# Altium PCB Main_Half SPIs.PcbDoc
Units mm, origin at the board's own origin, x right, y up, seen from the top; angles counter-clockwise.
Board outline 64.93 x 46.99 mm, 2 copper layers (Top Layer, Bottom Layer); 51 components, 38 nets, 223 pads, 38 vias.
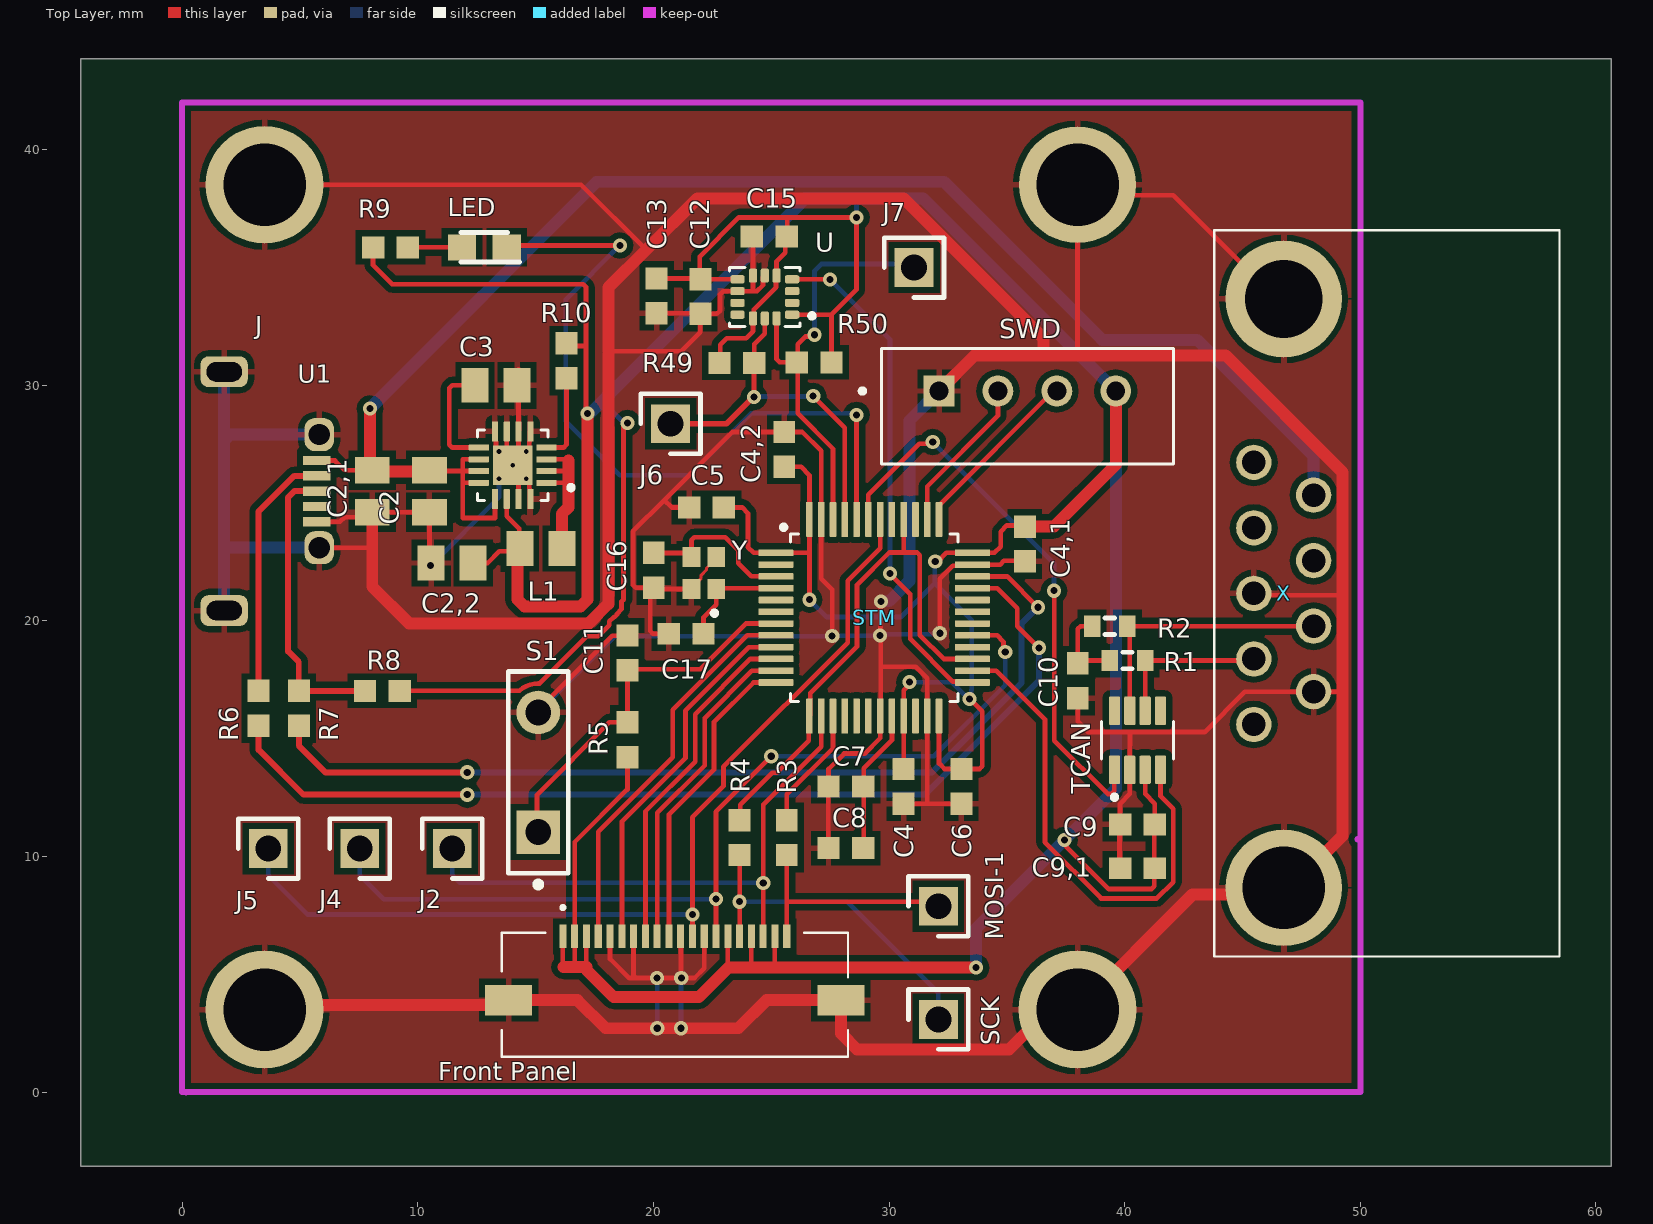
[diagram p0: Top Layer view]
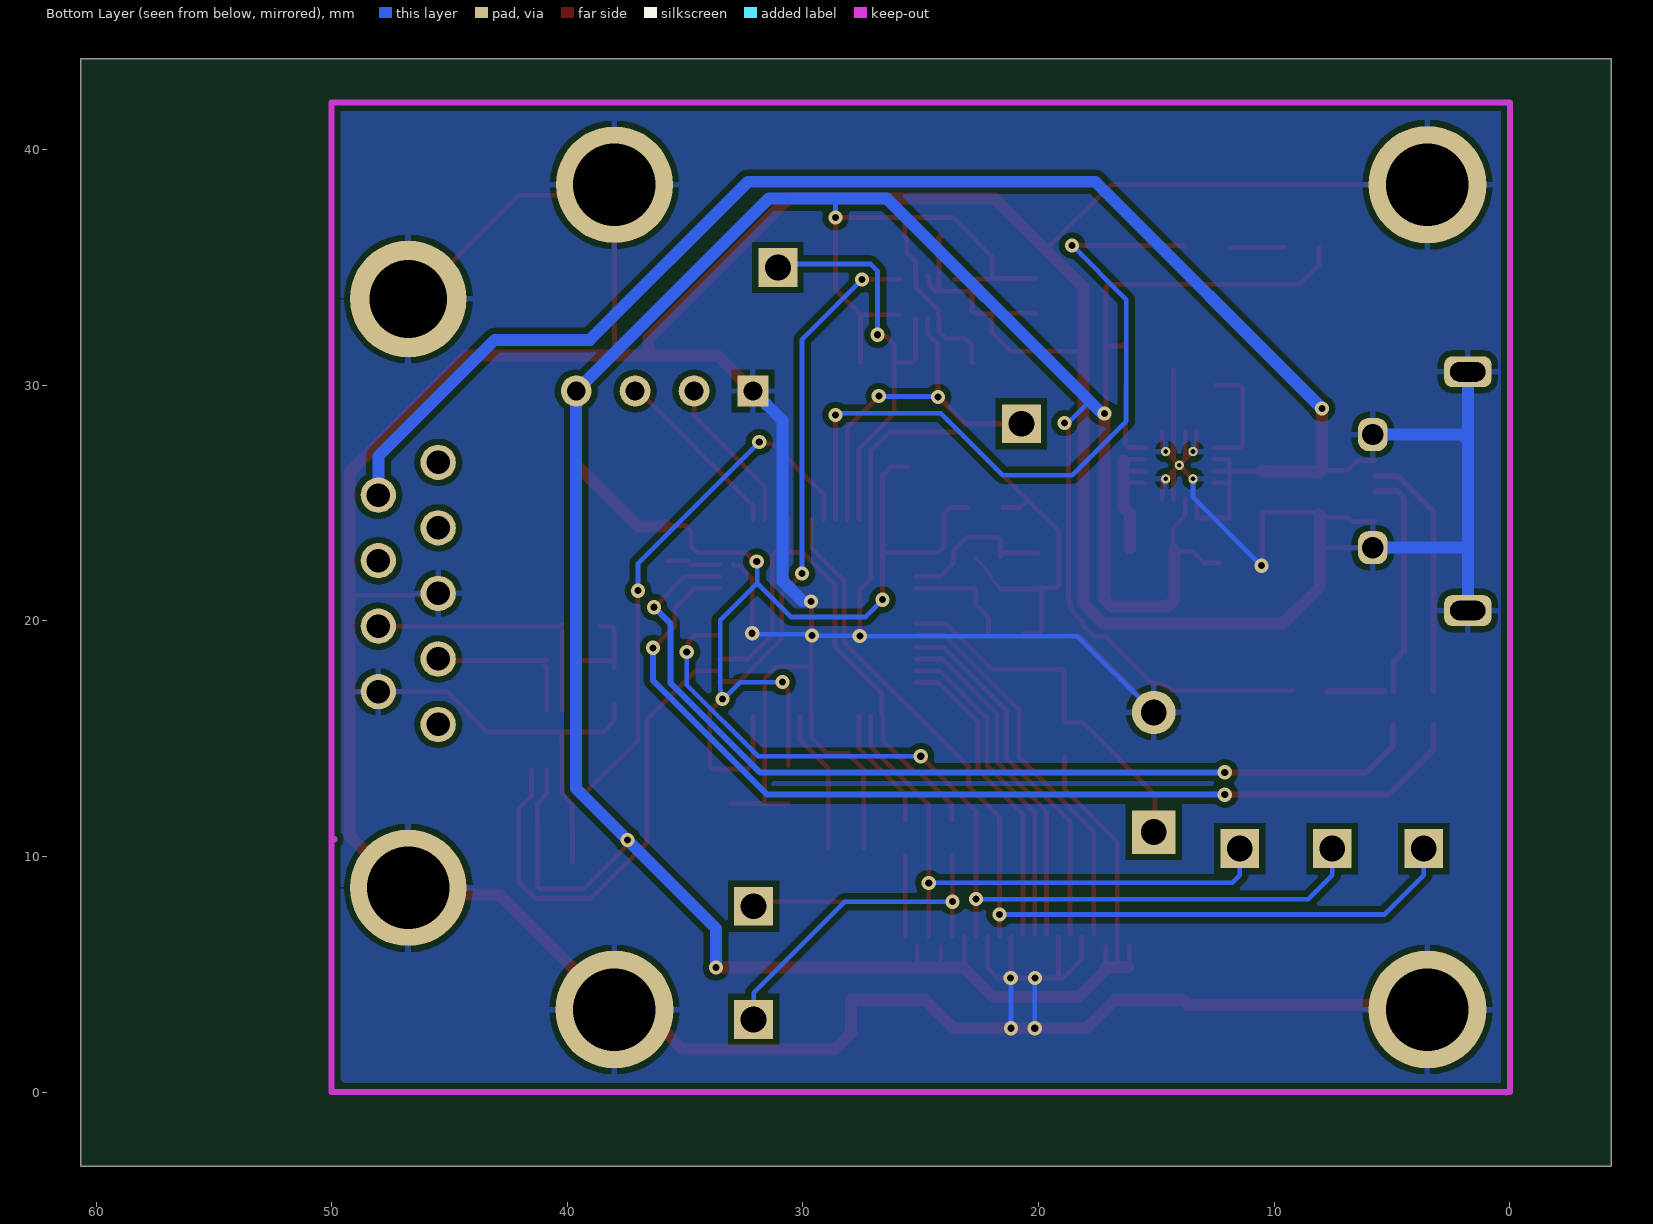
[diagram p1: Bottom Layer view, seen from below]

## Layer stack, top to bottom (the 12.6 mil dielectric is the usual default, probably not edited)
Top Solder: solder mask 0.0102, Solder Resist, Dk 3.5
Top Layer: signal copper 0.0356
Dielectric 1: dielectric 0.32, FR-4, Dk 4.8
Bottom Layer: signal copper 0.0356
Bottom Solder: solder mask 0.0102, Solder Resist, Dk 3.5

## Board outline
-4.291,-3.153 60.641,-3.153 60.641,43.841 -4.291,43.841

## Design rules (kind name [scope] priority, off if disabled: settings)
Clearance [All] p1: gap=0.254 ignorepadtopadclearanceinfootprint=TRUE except(0: Arc-Hole Track-Hole SMDPad-Hole THPad-Hole Fill-Hole Poly-Hole Region-Hole; 0.127: SMDPad-SMDPad SMDPad-THPad THPad-THPad; 0.15: Arc-Text Track-Text SMDPad-Text THPad-Text Via-Text Fill-Text Poly-Text Region-Text Text-Text Text-Hole; 0.2: Arc-Arc Arc-Track Arc-SMDPad Arc-THPad Track-Track Track-SMDPad Track-THPad; 0.5: Via-Hole)
ComponentClearance [All] p1: gap=0 collisioncheckmode=3 verticalgap=0 showdistances=FALSE
DiffPairsRouting TCAN [InDifferentialPair('TCAN')] p1: maxlimit=0.254 minlimit=0.254 mostfreqgap=0.254 toplayer_minwidth=0.2 toplayer_maxwidth=0.381 toplayer_prefwidth=0.2 bottomlayer_minwidth=0.2 bottomlayer_maxwidth=0.381 bottomlayer_prefwidth=0.2 maxuncoupledlength=12.7
HoleSize [All] p1: absolutevalues=TRUE maxlimit=4 minlimit=0.025 maxpercent=80.000 minpercent=20.000
HoleToHoleClearance [All] p1: gap=0.5 allowstackedmicrovias=TRUE
MatchedLengths MatchedLengths_1 [InDifferentialPair ('TCAN')] p1: tolerance=25.4 checknetsindiffpair=FALSE checkdiffpairvsdiffpair=TRUE checkxsignals=TRUE checkothers=TRUE
MatchedLengths CANMatchedLengths [InDifferentialPair ('TCAN')] p2: tolerance=25.4 checknetsindiffpair=FALSE checkdiffpairvsdiffpair=TRUE checkxsignals=TRUE checkothers=TRUE
MatchedLengths [InDifferentialPair ('NewDifferentialPair1')] p3: tolerance=25.4 checknetsindiffpair=FALSE checkdiffpairvsdiffpair=TRUE checkxsignals=TRUE checkothers=TRUE
MinimumSolderMaskSliver [All] p1: minsoldermaskwidth=0.2
PlaneConnect PlaneConnect_1 [All] p1: planeconnectstyle=Relief reliefexpansion=0.508 reliefentries=4 reliefconductorwidth=0.254 reliefairgap=0.254
PlaneConnect PlaneConnect_2 [IsPad] p2: planeconnectstyle=Relief reliefexpansion=0.508 reliefentries=4 reliefconductorwidth=0.254 reliefairgap=0.254
PlaneConnect [All] p3: planeconnectstyle=Relief reliefexpansion=0.508 reliefentries=4 reliefconductorwidth=0.254 reliefairgap=0.254
PolygonConnect PolygonConnect_2 [ispad] p1: thpad.connectstyle=Relief thpad.reliefconductorwidth=0.254 thpad.reliefentries=4 thpad.polygonreliefangle="90 Angle" thpad.airgapwidth=0.254 smdpad.connectstyle=Relief smdpad.reliefconductorwidth=0.254 smdpad.reliefentries=4 smdpad.polygonreliefangle="90 Angle" smdpad.airgapwidth=0.254 via.connectstyle=Direct via.reliefconductorwidth=0.254 via.reliefentries=4 via.polygonreliefangle="90 Angle" via.airgapwidth=0.254
PolygonConnect PolygonConnect_1 [All] p2: connectstyle=Direct reliefconductorwidth=0.254 reliefentries=4 polygonreliefangle="90 Angle" airgapwidth=0.254
PolygonConnect [All] p3: connectstyle=Relief reliefconductorwidth=0.254 reliefentries=4 polygonreliefangle="90 Angle" airgapwidth=0.254
RoutingTopology [All] p1: topology=Daisy_MidDriven
RoutingVias [All] p1: holewidth=0.3 width=0.6 viastyle="Through Hole" minholewidth=0.3 minwidth=0.6 maxholewidth=0.3 maxwidth=0.6
SolderMaskExpansion [All] p1: expansion=0.05 istentingtop=FALSE
Width Width_1 [All] p1: maxlimit=0.508 minlimit=0.127 preferedwidth=0.2
23 further rules are at their usual default settings.

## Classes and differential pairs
differential pair USB: +NetJ_3 -NetJ_2
differential pair USB1: +USB_DP -USB_DM
differential pair TCAN: +CAN_P -CAN_N

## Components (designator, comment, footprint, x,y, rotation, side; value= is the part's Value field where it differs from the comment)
C2 "Cap" INDC2012X55N 10.5,25.497 r270 top value=0.1uF
C2,1 "Cap" INDC2012X55N 8.072,25.497 r270 top value=10uF
C2,2 "Cap" INDC2012X55N 11.462,22.451 r0 top value=22uF
C3 "Cap" INDC2012X55N 13.325,29.989 r180 top value=3.3nF
C4 "Cap" CAPC1608X90N 30.624,12.971 r270 top value=100nF
C4,1 "Cap" CAPC1608X90N 35.765,23.258 r270 top value=100nF
C4,2 "Cap" CAPC1608X90N 25.555,27.271 r90 top value=100nF
C5 "Cap" CAPC1608X90N 22.257,24.807 r180 top value=10uF
C6 "Cap" CAPC1608X90N 33.073,12.971 r270 top value=1uF
C7 "Cap" CAPC1608X90N 28.171,12.971 r180 top value=1uF
C8 "Cap" CAPC1608X90N 28.171,10.349 r180 top value=100nF
C9 "Cap" CAPC1608X90N 40.543,11.354 r180 top value=100nF
C9,1 "Cap" CAPC1608X90N 40.543,9.497 r180 top value=100nF
C10 "Cap" CAPC1608X90N 38.01,17.456 r270 top value=4.7nF
C11 "Cap" CAPC1608X90N 18.9,18.635 r90 top value=100nF
C12 "Cap" CAPC1608X90N 20.141,33.785 r90 top value=0.1uF
C13 "Cap" CAPC1608X90N 21.996,33.759 r270 top value=2.22uF
C15 "Cap" CAPC1608X90N 24.917,36.299 r0 top value=10nF
C16 "Cap" CAPC1608X90N 20.017,22.14 r270 top value=8pF
C17 "Cap" CAPC1608X90N 21.389,19.448 r180 top value=8pF
"Front Panel" "5051102091" 5051102091 20.911,4.128 r0 top locked
J "47654-0001" USB_Conector 1.791,25.499 r270 top
J2 "90120-0761" HDRV1W90P0X254_1X1_232X249X560P 11.466,10.331 r90 top
J4 "90120-0761" HDRV1W90P0X254_1X1_232X249X560P 7.542,10.331 r90 top
J5 "90120-0761" HDRV1W90P0X254_1X1_232X249X560P 3.658,10.331 r90 top
J6 "90120-0761" HDRV1W90P0X254_1X1_232X249X560P 20.732,28.36 r90 top
J7 "90120-0761" HDRV1W90P0X254_1X1_232X249X560P 31.064,34.988 r90 top
L1 "Inductor" INDC2012X55N 15.23,23.063 r180 top value=1/2.2uH
LED "17-21_GHC-YR1S2_3T" LEDM2012X110N 12.827,35.847 r180 top
MOSI-1 "90120-0761" HDRV1W90P0X254_1X1_232X249X560P 32.094,7.884 r90 top (schematic designator J1)
R1 "Res3" J1-0603 40.118,18.309 r0 top value=60
R2 "Res3" J1-0603 39.368,19.77 r180 top value=60
R3 "Res" CAPC1608X90N 25.661,10.799 r90 top value=100
R4 "Res" CAPC1608X90N 23.661,10.799 r90 top value=100
R5 "Res" CAPC1608X90N 18.9,14.952 r270 top value=60
R6 "Res" CAPC1608X90N 3.253,16.29 r90 top value=22
R7 "Res" CAPC1608X90N 4.956,16.29 r90 top value=22
R8 "Res" CAPC1608X90N 8.501,17.025 r180 top value=1.5k
R9 "Res" CAPC1608X90N 8.845,35.847 r180 top value=1.5k
R10 "Res" CAPC1608X90N 16.313,31.031 r270 top value=100k (schematic designator R?)
R49 "Res" CAPC1608X90N 23.546,30.94 r180 top value=10k
R50 "Res" CAPC1608X90N 26.822,30.965 r0 top value=10k
S1 "SW-PB" SPST-2 15.115,13.568 r90 top
SCK "90120-0761" HDRV1W90P0X254_1X1_232X249X560P 32.094,3.082 r90 top (schematic designator J3)
STM "STM32G473CET6" QFP50P900X900X160-48N 29.374,20.13 r0 top value=Value
SWD "22-03-5045" MOLEX_22-03-5045 35.874,29.099 r0 top
TCAN "TCAN332GD" SOT65P280X145-8N 40.543,14.927 r90 top
U "ICM-42605" PQFN50P300X250X97-14N 24.73,33.738 r180 top
U1 "TPS62132RGTR" QFN50P300X300X100-17N 14.03,26.6 r180 top
X "DSUB9" 23018431 45.48,15.6 r90 top
Y "ECS-160-9-37-CKM-TR" XTAL_ECS-160-9-37-CKM-TR 22.143,22.022 r90 top

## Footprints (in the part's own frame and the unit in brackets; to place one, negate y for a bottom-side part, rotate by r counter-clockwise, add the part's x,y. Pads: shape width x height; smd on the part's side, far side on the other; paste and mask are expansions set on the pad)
23018431 [mm]
  round 1.5 hole 1: 1(0,0) 2(2.78,0) 3(5.56,0) 4(8.34,0) 5(11.12,0) 6(1.39,-2.54) 7(4.17,-2.54) 8(6.95,-2.54) 9(9.73,-2.54)
  round 4.95 hole 3.5 paste+0: MH2(-6.935,-1.27)
  round 4.95 hole 3.3 mask+0.05: MH2(18.055,-1.27)
  silkscreen extent -9.85,-12.97 20.96,1.68, body extent -9.86,-18.95 20.95,1.7, height 13.59
5051102091 [mm]
  rect 0.3x1 smd: 1(-4.75,2.475) 2(-4.25,2.475) 3(-3.75,2.475) 4(-3.25,2.475) 5(-2.75,2.475) 6(-2.25,2.475) 7(-1.75,2.475) 8(-1.25,2.475) 9(-0.75,2.475) 10(-0.25,2.475) 11(0.25,2.475) 12(0.75,2.475) 13(1.25,2.475) 14(1.75,2.475) 15(2.25,2.475) 16(2.75,2.475) 17(3.25,2.475) 18(3.75,2.475) 19(4.25,2.475) 20(4.75,2.475)
  rect 2x1.3 smd: MP1(-7.05,-0.225) MP2(7.05,-0.225)
  silkscreen extent -7.35,-2.63 7.35,3.75, body extent -7.75,-2.64 7.75,2.66, height 1.88
CAPC1608X90N [mm]
  rect 0.95x0.93 smd: 1(-0.738,0) 2(0.738,0)
HDRV1W90P0X254_1X1_232X249X560P [mm]
  rect 1.65x1.65 hole 1.1: 1(0,0)
  silkscreen extent -1.27,-1.27 1.27,1.27, body extent -1.27,-1.25 1.27,1.25, height 9.25
INDC2012X55N [mm]
  rect 1.14x1.47 smd: 1(-0.89,0) 2(0.89,0)
J1-0603 [mm] "Chip Resistor, Body 1.6x0.8mm, IPC High Density"
  rect 0.7x0.9 smd: 1(-0.75,0) 2(0.75,0)
  silkscreen extent -0.2,-0.35 0.2,0.35, body extent -0.85,-0.48 0.85,0.48, height 0.9
LEDM2012X110N [mm]
  rect 1.2x1.1 smd: 1(-0.95,0) 2(0.95,0)
  silkscreen extent -1.5,-0.63 1,0.63
MOLEX_22-03-5045 [mm]
  rect 1.308x1.308 hole 0.8: 1(-3.75,0.65)
  round 1.308 hole 0.8: 2(-1.25,0.65) 3(1.25,0.65) 4(3.75,0.65)
  silkscreen extent -7.1,-2.45 6.2,2.45
PQFN50P300X250X97-14N [mm]
  rrect50% 0.61x0.35 smd: 1(-1.16,0.75) 2(-1.16,0.25) 3(-1.16,-0.25) 4(-1.16,-0.75) 8(1.16,-0.75) 9(1.16,-0.25) 10(1.16,0.25) 11(1.16,0.75)
  rrect50% 0.35x0.61 smd: 5(-0.5,-0.91) 6(0,-0.91) 7(0.5,-0.91) 12(0.5,0.91) 13(0,0.91) 14(-0.5,0.91)
  silkscreen extent -2.1,-1.25 1.5,1.25
QFN50P300X300X100-17N [mm]
  rrect25% 0.86x0.26 smd: 1(-1.435,0.75) 2(-1.435,0.25) 3(-1.435,-0.25) 4(-1.435,-0.75) 9(1.435,-0.75) 10(1.435,-0.25) 11(1.435,0.25) 12(1.435,0.75)
  rrect25% 0.26x0.86 smd: 5(-0.75,-1.435) 6(-0.25,-1.435) 7(0.25,-1.435) 8(0.75,-1.435) 13(0.75,1.435) 14(0.25,1.435) 15(-0.25,1.435) 16(-0.75,1.435)
  rect 1.68x1.68 smd paste-2: 17(0,0)
  round 0.4 hole 0.2 mask+0: 18(0,0) 19(-0.58,0.58) 20(0.58,0.58) 21(-0.58,-0.58) 22(0.58,-0.58)
  silkscreen extent -2.57,-1.5 1.5,1.5
QFP50P900X900X160-48N [mm]
  rrect25% 1.49x0.28 smd: 1(-4.17,2.75) 2(-4.17,2.25) 3(-4.17,1.75) 4(-4.17,1.25) 5(-4.17,0.75) 6(-4.17,0.25) 7(-4.17,-0.25) 8(-4.17,-0.75) 9(-4.17,-1.25) 10(-4.17,-1.75) 11(-4.17,-2.25) 12(-4.17,-2.75) 25(4.17,-2.75) 26(4.17,-2.25) 27(4.17,-1.75) 28(4.17,-1.25) 29(4.17,-0.75) 30(4.17,-0.25) 31(4.17,0.25) 32(4.17,0.75) 33(4.17,1.25) 34(4.17,1.75) 35(4.17,2.25) 36(4.17,2.75)
  rrect25% 0.28x1.49 smd: 13(-2.75,-4.17) 14(-2.25,-4.17) 15(-1.75,-4.17) 16(-1.25,-4.17) 17(-0.75,-4.17) 18(-0.25,-4.17) 19(0.25,-4.17) 20(0.75,-4.17) 21(1.25,-4.17) 22(1.75,-4.17) 23(2.25,-4.17) 24(2.75,-4.17) 37(2.75,4.17) 38(2.25,4.17) 39(1.75,4.17) 40(1.25,4.17) 41(0.75,4.17) 42(0.25,4.17) 43(-0.25,4.17) 44(-0.75,4.17) 45(-1.25,4.17) 46(-1.75,4.17) 47(-2.25,4.17) 48(-2.75,4.17)
  silkscreen extent -3.94,-3.55 3.55,3.94
SOT65P280X145-8N [mm]
  rrect25% 1.21x0.48 smd: 1(-1.255,0.975) 2(-1.255,0.325) 3(-1.255,-0.325) 4(-1.255,-0.975) 5(1.255,-0.975) 6(1.255,-0.325) 7(1.255,0.325) 8(1.255,0.975)
  silkscreen extent -2.51,-1.54 0.8,1.54, body extent -1.4,-1.45 1.4,1.45, height 1.45
SPST-2 [mm] "Switch; 2 Leads"
  rect 1.85x1.85 hole 1.1: 1(-2.54,0)
  round 1.85 hole 1.1: 2(2.54,0)
  silkscreen extent -4.89,-1.27 4.28,1.27
USB_Conector [mm]
  rect 0.4x1.15 smd: 1(-1.3,3.925) 2(-0.65,3.925) 3(0,3.925) 4(0.65,3.925) 5(1.3,3.925)
  rrect50% 1.3x2 hole 1.5 slot 0.83 at 0 deg: 6(-5.065,0) 9(5.065,0)
  rrect70% 1.4x1.25 hole 0.9: 7(-2.4,4.03) 8(2.4,4.03)
XTAL_ECS-160-9-37-CKM-TR [mm]
  rect 0.85x0.75 smd: 1(-0.675,-0.525) 2(0.675,-0.525) 3(0.675,0.525) 4(-0.675,0.525)
  silkscreen extent -1.8,-0.55 -1.6,-0.35, body extent -1,-0.8 1,0.8, height 0.55

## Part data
C2 C2,1 C2,2 C3 C4 C4,1 C4,2 C5 C6 C7 C8 C9 C9,1 C10 C11 C12 C13 C15 C16 C17: "Capacitor"
"Front Panel": "Connector", Manufacturer_Name=Molex
J: library part 10118194-0001LF, "USB - micro B USB 2.0 Receptacle Connector 5 Position Surface Mount, Right Angle; Through Hole", Package=None
J2 J4 J5 J6 J7 MOSI-1 SCK: "Connector", Manufacturer_Name=Molex, Mouser Part Number=538-90120-0761
LED: "LED", Arrow Part Number=17-21/GHC-YR1S2/3T, Manufacturer_Name=Everlight, Mouser Part Number=N/A
R1 R2: "Resistor"
R3 R4 R5 R6 R7 R8 R9 R10 R49 R50: library part Res1, "Resistor"
S1: "Switch"
STM: library part STM32G4_LQFP48_T, "No Description Available", Manufacturer_Part_Number=stm32g4_lqfp48_t1
SWD: "Connector Header Through Hole 4 position 0.098 _2.50mm_", Package="QFP-208 Molex"
TCAN: "3.3-V CAN Transceivers with CAN FD (Flexible Data Rate) 8-SOIC -40 to 125", Package="SOIC-8 Texas Instruments"
U: "Accelerometer, Gyroscope, 6 Axis Sensor IÂ²C, I3Câ„ , SPI Output", Package="- TDK InvenSense"
U1: Package=None
X: "Connector Cap _Cover_, Screen For D-Sub Connectors, Female", Package=None
Y: "16MHz Â±10ppm Crystal 9pF 100 Ohms 4-SMD, No Lead", Package="SMD-4 ECS International"

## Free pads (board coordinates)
  round 5 hole 3.5 paste+0 mask+0.05: 2(38,3.5) 4(3.5,3.5) 5(3.5,38.5)
  round 4.95 hole 3.5 paste+0 mask+0.05: 3(38,38.5)

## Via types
v1: diameter 0.6, hole 0.3, Top Layer to Bottom Layer, tented both sides, 37 vias
v2: diameter 0.6, hole 0.3, Top Layer to Bottom Layer, 1 vias

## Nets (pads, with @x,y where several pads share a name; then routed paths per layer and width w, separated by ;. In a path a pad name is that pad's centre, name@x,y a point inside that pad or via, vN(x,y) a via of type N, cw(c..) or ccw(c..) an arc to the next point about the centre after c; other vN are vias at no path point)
3V3: "Front Panel.1" "Front Panel.2" "Front Panel.3" "Front Panel.15" "Front Panel.17" "Front Panel.19" C2,2.2 C4,1.1 C4,2.1 C4.1 C5.1 C6.1 C9,1.1 C9.1 C12.2 C13.1 C15.2 L1.2 R5.2 R8.1 R9.2 R10.1 R49.2 R50.2 STM.1 STM.21 STM.24 STM.36 STM.48 SWD.4 TCAN.3 U1.14 U.1 U.5 U.8 U.12 | length 233.9
  Top Layer w0.127: 23.161,5.51 23.39,5.281
  Top Layer w0.2: R9.2 8.107,35.082 8.913,34.276 17.028,34.276 17.145,34.159 v1@17.145,28.626 ; R8.1 14.302,17.025 cw(c15.115,16.108) 15.124,17.333 15.168,17.333 17.173,19.338 17.656,19.338 18.135,19.816 18.135,19.972 18.31,20.148 18.345,20.148 18.462,20.265 18.462,20.299 18.647,20.485 18.647,20.812 18.735,20.9 18.735,28.271 18.852,28.389 v1(18.901,28.389) ; 12.352,22.451 12.967,22.451 13.462,22.946 14.187,22.946 14.24,22.999 L1.2@14.304,23.063 ; U1.14 13.78,24.435 14.304,23.911 L1.2@14.304,23.063 ; L1.2 L1.2@14.304,23.063 ; 16.154,5.327 16.154,6.189 ; R10.1 16.427,31.655 17.028,31.655 ; 16.661,6.603 16.661,5.314 16.674,5.3 ; 16.668,6.63 16.668,10.611 18.9,12.843 R5.2 ; 17.154,5.198 17.154,5.3 17.154,6.189 ; C12.2 C13.1@21.97,34.523 ; R49.2 22.837,30.968 22.837,31.705 23.125,31.993 23.942,31.993 24.23,32.281 U.12 24.255,32.853 24.255,33.206 25.205,34.156 25.205,34.623 U.5 25.23,35.253 25.595,35.617 25.595,36.24 C15.2 25.682,36.326 25.682,37.112 ; C5.1 23.77,24.807 24.016,24.561 24.016,23.126 24.262,22.88 STM.1 26.623,22.88 ; 23.161,5.51 23.161,6.603 ; U.8 22.005,34.488 C13.1 C13.1@21.97,34.523 ; 24.154,5.281 24.154,6.189 ; 25.154,5.281 25.154,6.189 ; 25.555,26.533 26.27,26.533 26.623,26.179 STM.48 26.623,22.88 ; U.1 27.56,32.988 ; v1(26.623,20.893) 26.623,22.88 ; R50.2 27.56,32.988 ; C4.1@30.624,13.847 STM.21 30.624,17.047 30.863,17.287 v1(30.863,17.395) ; v1(31.962,22.511) 32.07,22.511 32.438,22.88 STM.36 34.473,22.88 34.737,23.143 34.737,23.781 35,24.045 35.716,24.045 35.765,23.996 35.832,24.063 ; STM.24 32.124,13.943 32.358,13.709 C6.1 33.838,13.709 33.955,13.826 33.955,16.15 v1(33.42,16.686) ; v1@37.52,10.418 39.323,8.615 41.138,8.615 41.256,8.732 41.256,9.728 C9.1@41.256,11.354 ; TCAN.3 40.868,12.649 41.281,12.236 C9.1 ; C13.1@21.97,34.523 21.97,35.455 23.627,37.112 25.682,37.112 ; 25.682,37.112 v1(28.617,37.112) 28.617,34.045 27.56,32.988
  Top Layer w0.5: 17.154,5.198 18.32,4.032 21.93,4.032 23.179,5.281 23.39,5.281
  Top Layer w0.508: L1.2@14.24,22.999 14.24,20.898 14.538,20.6 16.902,20.6 17.2,20.898 v1(17.2,28.8) ; 16.195,5.3 16.674,5.3 17.154,5.3 ; 23.39,5.281 24.154,5.281 25.154,5.281 v1(33.696,5.281) ; 35.832,24.063 35.899,23.996 36.992,23.996 39.624,26.627 SWD.4
  Bottom Layer w0.2: 17.956,29.437 17.956,29.197 18.764,28.389 v1(18.901,28.389) ; v1(26.623,20.893) 27.362,20.155 30.502,20.155 31.943,21.597 ; v1(28.617,37.112) 28.624,37.12 28.624,37.92 ; v1(30.863,17.395) 32.658,17.395 33.368,16.686 v1(33.42,16.686) 33.496,16.762 33.496,17.071 33.511,17.086 33.511,20.029 31.943,21.597 ; v1(31.962,22.511) 31.943,22.493 31.943,21.597
  Bottom Layer w0.508: v1(17.2,28.8) 17.319,28.8 v1@17.364,28.844 ; v1@17.385,28.866 17.956,29.437 26.439,37.92 28.624,37.92 31.452,37.92 SWD.4 39.624,12.873 v1(37.443,10.693) ; v1(33.696,5.281) 33.696,6.946 v1@37.413,10.663
CAN_N: R1.2 TCAN.6 X.2 | length 6.7
  Top Layer w0.2: TCAN.6 40.868,17.992 R1.2@40.968,18.092 ; R1.2@40.94,18.38 R1.2 45.409,18.309 X.2 ; R1.2@40.999,18.061 R1.2@41.034,18.096
CAN_P: R2.1 TCAN.7 X.7 | length 11.2
  Top Layer w0.2: TCAN.7 40.218,19.555 R2.1@40.225,19.562 ; R2.1@40.218,19.866 40.315,19.77 47.812,19.77 X.7@47.916,19.666
DEC_A0: "Front Panel.4" STM.8 | length 16.5
  Top Layer w0.2: 17.667,6.706 17.667,11.044 20.828,14.205 20.828,16.219 23.989,19.38 STM.8@25.191,19.38
DEC_A1: "Front Panel.6" STM.9 | length 15.5
  Top Layer w0.2: 18.667,6.706 18.667,11.479 21.361,14.173 21.361,16.186 24.054,18.88 STM.9@25.191,18.88
DEC_A2: "Front Panel.8" STM.10 | length 14.6
  Top Layer w0.2: 19.667,6.706 19.667,11.913 21.776,14.023 21.776,16.036 24.12,18.38 STM.10@25.191,18.38
DEC_E3_1: "Front Panel.9" STM.11 | length 13.9
  Top Layer w0.2: 20.167,6.706 20.167,11.847 22.176,13.857 22.176,15.87 24.186,17.88 STM.11
DEC_E3_2: "Front Panel.10" STM.12 | length 13.1
  Top Layer w0.2: 20.667,6.706 20.667,11.782 22.576,13.691 22.576,15.704 24.251,17.38 STM.12
GND: "Front Panel.5" "Front Panel.7" "Front Panel.11" "Front Panel.13" "Front Panel.MP1" "Front Panel.MP2" C2,1.2 C2,2.1 C2.2 C3.1 C4,1.2 C4,2.2 C4.2 C5.2 C6.2 C7.2 C8.2 C9,1.2 C9.2 C10.2 C11.2 C12.1 C13.2 C15.1 C16.2 C17.2 J.5 J.6 J.7 J.8 J.9 pad.2 pad.3 pad.4 pad.5 S1.2 STM.19 STM.23 STM.35 STM.47 SWD.1 TCAN.2 U1.5 U1.6 U1.7 U1.8 U1.15 U1.16 U1.17 U1.18 U1.19 U1.20 U1.21 U1.22 U.6 U.7 U.9 X.3 X.6 X.MH2 Y.2 Y.4 | length 359.7
  Top Layer w0.127: Y.4 21.618,21.397 22.029,21.808 22.029,21.935 22.256,22.162 22.256,22.235 22.668,22.647 Y.2
  Top Layer w0.2: pad.5 16.93,38.5 19.691,35.738 ; J.5 6.702,24.199 6.9,24.397 7.959,24.397 8.072,24.51 ; J.8 7.953,23.099 8.072,22.98 ; 8.072,24.607 C2.2 v2@10.5,22.415 ; v2(10.55,22.336) 10.557,22.343 v2@10.572,22.343 ; U1.8 13.31,28.005 13.31,27.6 13.325,27.585 13.325,27.305 U1.22 U1.17@13.78,26.85 ; U1.17@13.5,26.07 U1.17 ; U1.7 U1.17@13.78,26.85 ; U1.15 U1.17@14.28,26.35 ; C3.1@14.287,30.671 14.28,30.664 14.28,29.215 U1.6 14.28,26.93 U1.17@14.32,26.89 ; U1.16 14.75,25.195 14.75,25.6 14.735,25.615 14.735,25.895 U1.19 U1.17@14.28,26.35 ; U1.5 14.75,28.005 14.75,27.6 14.735,27.585 14.735,27.305 U1.21 U1.17@14.32,26.89 ; S1.2 15.115,16.231 18.252,19.368 18.895,19.368 C11.2 ; 17.956,31.437 18.093,31.437 21.186,31.437 21.996,32.246 C13.2 22.694,33.021 22.83,33.157 22.83,33.852 22.965,33.988 U.9 24.23,33.988 ; 18.161,6.603 18.161,5.649 18.974,4.836 19.257,4.836 ; 19.161,6.603 19.161,4.932 19.257,4.836 ; C12.1 C13.2@21.97,33.047 ; C17.2 19.982,19.448 19.865,19.565 19.865,21.25 C16.2 ; 21.161,6.603 21.173,6.591 21.173,4.853 v1(21.186,4.84) 21.746,4.84 22.161,5.255 22.161,6.603 ; v1@21.184,4.838 20.163,4.838 v1(20.161,4.836) 19.257,4.836 ; C5.2 20.78,24.807 20.467,25.12 ; Y.4 20.073,21.347 C16.2 ; C15.1@24.23,36.247 U.7 24.23,33.988 ; U.6 24.655,34.573 24.655,34.247 24.396,33.988 24.23,33.988 ; C8.2 27.417,10.365 27.417,12.955 C7.2 27.433,13.706 28.092,14.365 28.964,14.365 29.623,15.025 STM.19 29.654,15.99 29.654,18.049 ; v1(27.59,19.346) 27.59,21.321 27.124,21.788 STM.47 27.124,27.205 26.32,28.009 25.555,28.009 23.356,28.009 20.467,25.12 ; v1(29.659,20.809) 29.641,20.791 29.641,19.39 v1(29.623,19.372) 29.654,19.342 29.654,18.049 ; C4.2 31.624,12.233 ; v1(32.155,19.47) 32.155,21.78 32.715,22.34 32.917,22.34 STM.35@32.971,22.394 ; C6.2 31.624,12.233 ; STM.35 34.711,22.38 34.878,22.547 35.738,22.547 35.765,22.52 ; 38,31.259 pad.3 38.439,38.061 42.06,38.061 X.MH2@46.75,33.371 ; C10.2@38.01,16.504 38.01,15.729 38.462,15.277 40.225,15.277 ; 39.78,9.728 39.78,11.328 C9.2 39.805,12.236 40.218,12.649 TCAN.2 40.218,14.724 40.225,14.73 40.225,15.277 ; X.3@45.48,20.876 X.3@45.56,20.796 ; X.3 45.56,21.08 49.243,21.08 ; 49.243,16.99 X.6 45.105,16.99 43.392,15.277 40.225,15.277 ; U1.17@13.78,26.85 U1.17 ; U1.17 U1.17@14.28,26.35 ; U1.17 U1.17@14.32,26.89 ; C16.2 19.252,21.402 19.135,21.519 19.135,23.788 20.467,25.12 ; 29.654,18.049 31.134,18.049 31.624,17.56 STM.23 31.624,12.233
  Top Layer w0.254: C13.2@21.97,33.047 C13.2 ; C15.1 C15.1@24.23,36.247
  Top Layer w0.508: pad.4 3.701,3.701 13.659,3.701 13.861,3.903 16.777,3.903 17.972,2.707 v1(20.167,2.707) v1(21.167,2.707) 23.606,2.707 24.801,3.903 27.961,3.903 27.961,2.491 28.649,1.803 35.088,1.803 36.284,3 pad.2@39,3 ; 8.072,24.51 8.072,22.98 8.072,21.45 9.63,19.892 17.271,19.892 18.093,20.714 18.093,31.299 ; 18.093,31.437 18.093,34.14 19.691,35.738 21.873,37.92 30.622,37.92 36.565,31.977 36.565,31.259 ; SWD.1 33.633,31.259 36.565,31.259 ; pad.2 42.881,8.381 46.75,8.381 49.243,10.874 49.243,16.99 49.243,21.08 49.243,26.298 44.283,31.259 41.783,31.259 39.627,31.259 38,31.259 36.565,31.259
  Bottom Layer w0.127: v1@20.164,2.71 v1(20.167,2.707) ; v1(21.167,2.707) v1@21.176,2.717
  Bottom Layer w0.2: v2(10.55,22.336) 13.45,25.237 U1.20 ; S1.2 18.353,19.346 v1(27.59,19.346) 27.603,19.359 29.61,19.359 v1(29.623,19.372) 29.672,19.421 32.106,19.421 v1(32.155,19.47) ; v1@20.164,2.71 v1@20.164,4.833 ; v1@21.176,2.717 v1@21.176,4.831
  Bottom Layer w0.508: J.9 1.791,23.155 ; J.6 1.791,27.636 ; J.8 1.847,23.099 1.791,23.155 ; J.7 2.053,27.899 1.791,27.636 ; v1(29.659,20.809) 29.677,20.827 30.005,20.827 30.864,21.686 30.864,28.49 SWD.1 ; 1.791,23.155 1.791,27.636
INT: STM.25 U.4 | length 21.7
  Top Layer w0.2: U.4 v1(27.49,34.488) ; v1(30.038,22.002) 30.908,21.132 30.908,19.227 32.715,17.42 33.504,17.42 STM.25
  Bottom Layer w0.2: v1(27.49,34.488) 30.038,31.94 v1(30.038,22.002)
LED: LED.1 STM.44 | length 32.1
  Top Layer w0.2: LED.1 13.855,35.925 v1(18.58,35.925) ; STM.44 v1(28.623,28.736)
  Bottom Layer w0.2: v1(18.58,35.925) 16.283,33.629 16.283,28.473 18.584,26.171 21.518,26.171 24.147,28.8 28.559,28.8 v1(28.623,28.736)
MISO-1: "Front Panel.18" J2.1 STM.14 | length 24.8
  Top Layer w0.2: 24.661,6.603 24.663,6.605 24.663,8.876 v1(24.665,8.878) 24.665,12.202 27.124,14.66 STM.14
  Bottom Layer w0.2: J2.1 11.466,9.206 11.794,8.878 v1(24.665,8.878)
MOSI-1: R3.2 STM.15 | length 5.2
  Top Layer w0.2: R3.2 25.661,12.632 27.623,14.595 STM.15
MOSI-2: "Front Panel.14" J4.1 STM.29 | length 39.8
  Top Layer w0.2: 22.658,6.606 22.658,8.183 v1(22.654,8.186) 22.654,11.9 v1(25.003,14.249) ; STM.29 34.589,19.38 34.856,19.113 34.856,18.755 v1(34.932,18.679)
  Bottom Layer w0.2: J4.1 7.542,9.206 8.562,8.186 v1(22.654,8.186) ; v1(25.003,14.249) 31.908,14.249 34.932,17.273 v1(34.932,18.679)
MOSI-3: "Front Panel.12" J5.1 STM.42 | length 40.8
  Top Layer w0.2: 21.661,6.603 v1(21.661,7.532) 21.661,11.666 22.976,12.982 22.976,13.808 28.244,19.075 28.244,21.698 29.623,23.078 STM.42
  Bottom Layer w0.2: J5.1 3.658,9.206 5.332,7.532 v1(21.661,7.532)
NetC3_2: C3.2 U1.9 | length 4.9
  Top Layer w0.2: C3.2@12.521,29.989 C3.2 11.462,29.989 11.344,29.872 11.344,27.467 11.462,27.35 U1.9
NetC7_1: C7.1 C8.1 STM.20 | length 6.1
  Top Layer w0.2: C7.1 C7.1@28.933,12.947 ; C8.1@28.933,10.349 C7.1@28.933,12.947 ; STM.20@30.124,15.934 30.124,14.927 29.528,14.331 28.933,13.736 C7.1@28.933,12.947
NetC10_1: C10.1 R1.1 R2.2 | length 3.7
  Top Layer w0.2: C10.1@38.01,17.98 C10.1 C10.1@38.01,18.306 ; R2.2 38.127,19.77 38.01,19.653 C10.1@38.01,18.306 ; R1.1 38.012,18.309 C10.1@38.01,18.306
NetC11_1: C11.1 R5.1 S1.1 STM.7 | length 16
  Top Layer w0.2: S1.1 15.064,11.079 15.064,12.62 18.135,15.69 R5.1 ; R5.1@18.9,15.715 C11.1 18.945,17.943 21.986,17.943 23.923,19.88 STM.7
NetC16_1: C16.1 STM.3 Y.3 | length 7
  Top Layer w0.2: C16.1 Y.3@21.618,22.878 ; Y.3 Y.3@21.618,22.878 ; STM.3 25.197,21.886 24.159,21.886 23.604,22.441 23.604,22.984 23.05,23.539 21.735,23.539 21.618,23.422 Y.3@21.618,22.878
NetC17_1: C17.1 STM.4 Y.1 | length 4.7
  Top Layer w0.2: C17.1 22.127,20.135 22.668,20.676 Y.1 ; Y.1@22.668,21.38 STM.4
"NetFront Panel_16": "Front Panel.16" R4.1 SCK.1 | length 14.6
  Top Layer w0.2: 23.661,6.61 v1(23.661,8.078) R4.1
  Bottom Layer w0.2: v1(23.661,8.078) 28.223,8.078 32.094,4.207 SCK.1
"NetFront Panel_20": "Front Panel.20" MOSI-1.1 R3.1 | length 10
  Top Layer w0.2: 25.661,6.603 25.661,8.078 ; R3.1 25.661,8.078 ; MOSI-1.1 31.9,8.078 25.661,8.078
NetJ_2: J.2 R6.2 | length 10.7
  Top Layer w0.254: R6.2 3.253,24.639 4.763,26.149 J.2 J.2@5.719,26.149
NetJ_3: J.3 R7.2 R8.2 | length 12.2
  Top Layer w0.254: R7.2 4.953,17.031 4.953,18.256 4.506,18.704 4.506,25.24 4.763,25.497 5.717,25.497 J.3@5.719,25.499 ; R7.2@5.311,17.025 R8.2
NetL1_1: L1.1 U1.1 U1.2 U1.3 | length 6.6
  Top Layer w0.2: U1.1 16.391,25.85 ; U1.2 16.391,26.35 ; U1.3 16.337,26.85 16.391,26.796
  Top Layer w0.508: L1.1 16.12,24.536 16.391,24.807 16.391,25.85 16.391,26.35 16.391,26.796
NetLED_2: LED.2 R9.1 | length 2.3
  Top Layer w0.2: R9.1 LED.2
NetR10_2: R10.2 U1.4 | length 3.4
  Top Layer w0.2: U1.4 16.196,27.35 16.313,27.467 R10.2@16.313,29.989
NetSTM_26: STM.26 TCAN.4 | length 20.8
  Top Layer w0.2: STM.26 34.554,17.88 36.615,15.818 36.615,10.597 38.997,8.215 41.364,8.215 42.056,8.907 42.056,12.027 41.518,12.565 TCAN.4
NetSTM_43: STM.43 TCAN.1 | length 24
  Top Layer w0.2: STM.43 29.124,25.345 31.285,27.506 31.78,27.506 v1(31.856,27.583) ; v1(36.999,21.275) 37.015,21.258 37.015,14.911 39.277,12.65 39.442,12.65 39.559,12.767 39.559,13.663 TCAN.1
  Bottom Layer w0.2: v1(31.856,27.583) 36.999,22.44 v1(36.999,21.275)
SCK-1: R4.2 STM.13 STM.27 STM.40 | length 22.9
  Top Layer w0.2: R4.2 23.687,11.563 23.687,12.195 25.042,13.55 25.229,13.55 26.593,14.915 26.593,15.93 STM.13 26.663,16 26.663,16.929 28.644,18.91 28.644,21.533 30.007,22.896 30.624,22.896 ; STM.40 30.624,22.896 ; STM.27 32.32,18.38 31.308,19.392 31.308,22.779 31.191,22.896 30.624,22.896
SCL-1: J6.1 R49.1 STM.45 U.13 | length 15.8
  Top Layer w0.2: v1@24.259,29.508 24.273,29.521 R49.1@24.273,30.901 ; R49.1 24.284,31.741 24.73,32.187 U.13 ; v1(26.783,29.533) 28.124,28.192 STM.45
  Top Layer w0.254: J6.1 23.103,28.36 24.251,29.508 v1@24.259,29.508 ; R49.1@24.259,30.915 R49.1
  Bottom Layer w0.2: v1(24.273,29.494) 24.292,29.514 26.764,29.514 v1(26.783,29.533)
SDA-1: J7.1 R50.1 STM.46 U.14 | length 18.7
  Top Layer w0.2: U.14 25.23,31.091 25.357,30.965 R50.1 26.127,31.009 26.127,31.73 26.455,32.058 26.76,32.058 v1(26.836,32.135) ; R50.1@26.127,30.921 26.127,28.8 27.623,27.304 STM.46
  Bottom Layer w0.2: v1(26.836,32.135) 26.836,34.839 27.139,35.142 30.93,35.142 J7.1@31.064,35.008
SWCLK: STM.38 SWD.2 | length 6.7
  Top Layer w0.2: STM.38 31.624,25.697 34.624,28.697 SWD.2
SWDIO: STM.37 SWD.3 | length 7.6
  Top Layer w0.2: STM.37 32.124,24.905 36.968,29.749 SWD.3
USB_DM: R6.1 STM.33 | length 42.6
  Top Layer w0.2: STM.33 34.589,21.38 35.437,20.531 35.437,19.776 v1(36.361,18.851)
  Top Layer w0.254: R6.1 3.253,14.519 5.154,12.618 v1(12.103,12.618)
  Bottom Layer w0.254: v1(12.103,12.618) 31.523,12.618 36.361,17.456 v1(36.361,18.851)
USB_DP: R7.1 STM.34 | length 40.4
  Top Layer w0.2: STM.34 35.013,21.88 v1(36.32,20.573)
  Top Layer w0.254: R7.1 4.956,14.696 6.083,13.568 v1(12.103,13.568)
  Bottom Layer w0.254: v1(12.103,13.568) 31.831,13.568 35.613,17.35 35.613,19.866 v1(36.32,20.573)
Vcc: C2,1.1 C2.1 J.1 U1.10 U1.11 U1.12 U1.13 X.9 | length 66.3
  Top Layer w0.2: J.1 6.488,26.799 6.9,26.387 7.975,26.387 8.072,26.29 ; C2.1@10.476,26.35 11.915,26.35 ; U1.12 11.945,25.85 11.915,25.88 ; U1.11 11.915,26.35 ; U1.10 11.915,26.85 11.915,26.35 ; U1.13 13.28,24.362 11.915,24.362 11.915,25.88 ; 11.915,25.88 11.915,26.35
  Top Layer w0.508: v1(7.975,29.006) 7.975,26.483 8.072,26.387 ; 8.072,26.29 8.12,26.338 10.452,26.338 C2.1
  Bottom Layer w0.508: v1(7.975,29.006) 17.597,38.628 32.334,38.628 39.045,31.918 41.773,31.918 43.078,31.918 48.02,26.975 X.9
pads on no net: J.4 STM.2 STM.5 STM.6 STM.16 STM.17 STM.18 STM.22 STM.28 STM.30 STM.31 STM.32 STM.39 STM.41 TCAN.5 TCAN.8 U.2 U.3 U.10 U.11 X.1 X.4 X.5 X.8

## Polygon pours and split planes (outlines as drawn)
GND on Top Layer "GND_L01_P001" (solid, remove dead copper, pour order 1): 0.388,41.612 0.388,0.388 49.612,0.388 49.612,41.612
GND on Bottom Layer "GND_L02_P002" (solid, pour order 2): 0.388,41.612 0.172,41.395 0.172,0.388 49.488,0.388 49.8,0.7 49.612,0.888 49.612,41.612

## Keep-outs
Keep-Out Layer:
  lines w0.254: 0.161,-0.011 0.172,0 ; 49.872,10.729 49.887,10.713 ; 0,0 50,0 50,42 0,42 0,0

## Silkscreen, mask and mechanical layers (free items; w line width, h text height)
Mechanical 6:
  lines w0.254: 0,0 50,0 50,42 0,42 0,0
